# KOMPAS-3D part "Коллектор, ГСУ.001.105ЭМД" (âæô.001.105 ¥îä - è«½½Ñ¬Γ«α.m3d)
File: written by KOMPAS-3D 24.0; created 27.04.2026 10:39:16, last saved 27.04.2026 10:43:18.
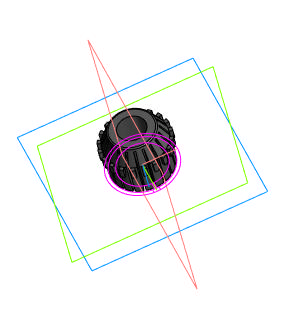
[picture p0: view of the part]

Document properties: Автор: USG_411; Полное имя файла: C:\Users\USG_411\Desktop\ГМ2704_411-15\ГСУ.001.105 ЭМД - Коллектор.m3d

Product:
- Part/product: Коллектор  | designation ГСУ.001.105ЭМД
    Масса: 0.020234

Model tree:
1. Эскиз:1
2. Элемент вращения:1
     Угол 1 = 360
3. Эскиз:3  (with: Грань.Элемент вращения:1)
4. Элемент выдавливания:2
     Расстояние 2 = 15.5
5. Фаска:2  (with: Ребро.Элемент вращения:1)
     Угол = 45; Длина 1 = 0.5; Длина 2 = 0.5
6. Скругление:2  (with: Ребро.Элемент вращения:1)
     Радиус = 0.5
7. Эскиз:4  (with: Грань.Элемент вращения:1, Ребро.Элемент вращения:1)
8. Элемент выдавливания:3
     Расстояние 2 = 15.5
9. Массив по концентрической сетке:1  (with: Элемент выдавливания:3, Эскиз:4, Грань.Элемент выдавливания:2)  (20 pattern instances)
     Шаг 2 = 360

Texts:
  ГСУ.001.105
  ГСУ.001.105 ЭМД
  Линейный размер с обрывом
